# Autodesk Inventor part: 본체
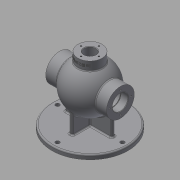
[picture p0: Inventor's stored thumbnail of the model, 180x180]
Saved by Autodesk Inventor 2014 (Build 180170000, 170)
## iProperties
Created: 2020-08
Part Number: 본체
Material: Generic
Document SubType Name: Modeling
Designer: kh
Density: 1 g/cm^3
Appearance: Default
Author: kh
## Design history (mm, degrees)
sketch "Sketch1"
  geometry: C1 r 85 at (0, 0); 1 further point
  constraints: 1 centre point, 1 coincident
  dimensions: "d0" = 170 diameter of C1
extrude "Extrusion1" new body sketch "Sketch1" distance "d1" = 10; taper "d2" = 0 deg
sketch "Sketch2"
  geometry: A1 r 72.5 centre (0, 0) between (0, 72.5) and (-72.5, 0); 3 further points
  constraints: 4 point on circle, 2 horizontal alignment, 2 vertical alignment, 1 centre point, 1 coincident
  dimensions: "d3" = 145 diameter of A1
hole "Hole1" sketch "Sketch2" at (0, 72.5), (-72.5, 0), (0, -72.5), (72.5, 0) diameter "d4" = 9; stored, may be unused: countersink angle "d8" = 90 deg, drill point angle "d10" = 118 deg; dims "d5" = 6, "d6" = 4, "d7" = 2, "d9" = 8
sketch "Sketch3"
  geometry: L1 (68, 10)-(68, 0) reference; L2 (68, 0)-(-68, 0) reference; L3 (-68, 0)-(-68, 10) reference; L4 (-68, 10)-(68, 10) reference; L5 (-85, 0)-(-85, 10) reference; L6 (-85, 10)-(-77, 10) reference; L7 (-77, 10)-(-77, 0) reference; L8 (-77, 0)-(-85, 0) reference; L9 (85, 10)-(85, 0) reference; L10 (85, 0)-(77, 0) reference; L11 (77, 0)-(77, 10) reference; L12 (77, 10)-(85, 10) reference; L13 (-53, 85)-(53, 85); A1 r 53 centre (0, 85) between (-53, 85) and (53, 85); 3 further points
  constraints: 2 end point, 2 midpoint, 2 point on circle, 1 centre point, 1 coincident, 1 parallel, 1 vertical alignment
  dimensions: "d11" = 85 distance of point (0, 0) A1.centre; "d12" = 106 diameter of A1
revolve "Revolution1" sketch "Sketch3" stored, may be unused: angle "d13" = 90 deg
workplane "Work Plane1"
sketch "Sketch4"
  geometry: L1 (51, 10)-(51, 0) reference; L2 (51, 0)-(0, 0) reference; L3 (0, 10)-(0, 0) reference; L4 (-51, 10)-(0, 10) reference; L5 (-51, 0)-(-51, 10) reference; L6 (0, 0)-(-51, 0) reference; L7 (0, 10)-(51, 10) reference; L8 (-85, 0)-(85, 0) reference; C1 r 31 at (0, 85)
  constraints: 1 centre point, 1 vertical alignment
  dimensions: "d15" = 62 diameter of C1; "d16" = 85 distance from line of L8 C1.centre
extrude "Extrusion2" join sketch "Sketch4" stored distance "d17" = 10; taper "d18" = 0 deg
mirror "Mirror1"
sketch "Sketch5"
  geometry: C1 r 31 at (0, 0) reference; C2 r 17.5 at (0, 0); 1 further point
  constraints: 1 centre point, 1 coincident
  dimensions: "d19" = 35 diameter of C2
extrude "Extrusion3" cut sketch "Sketch5" stored distance "d20" = 10; taper "d21" = 0 deg
sketch "Sketch6"
  geometry: L1 (-68, 0)-(-68, 10) reference; L2 (-68, 10)-(68, 10) reference; L3 (68, 10)-(68, 0) reference; L4 (68, 0)-(-68, 0) reference; L5 (85, 10)-(85, 0) reference; L6 (85, 0)-(77, 0) reference; L7 (77, 0)-(77, 10) reference; L8 (77, 10)-(85, 10) reference; L9 (-85, 0)-(-85, 10) reference; L10 (-85, 10)-(-77, 10) reference; L11 (-77, 10)-(-77, 0) reference; L12 (-77, 0)-(-85, 0) reference; L13 (-68, 116)-(-42.988, 116) reference; L14 (42.988, 116)-(68, 116) reference; L15 (68, 116)-(68, 102.5) reference; L16 (68, 102.5)-(-68, 102.5) reference; L17 (-68, 102.5)-(-68, 116) reference; L18 (-42.988, 54)-(-68, 54) reference; L19 (-68, 54)-(-68, 67.5) reference; L20 (-68, 67.5)-(68, 67.5) reference; L21 (68, 67.5)-(68, 54) reference; L22 (68, 54)-(42.988, 54) reference; L23 (-68, 85)-(68, 85); L24 (-52, 102.5)-(-50.25, 102.5); L25 (-50.25, 102.5)-(-50.25, 103.5); L26 (-50.25, 103.5)-(-52, 103.5); L27 (-52, 103.5)-(-52, 102.5); A1 r 53 centre (0, 85) between (42.988, 116) and (-42.988, 116) reference; A2 r 53 centre (0, 85) between (-42.988, 54) and (42.988, 54) reference; 2 further points
  constraints: 10 end point, 3 parallel, 1 coincident, 1 horizontal, 1 midpoint, 1 perpendicular, 1 point on line
  dimensions: "d22" = 16 distance between parallel lines of L27 L17; "d23" = 1.75 distance of L25.end L26.end; "d24" = 37 diameter of L26 L23
revolve "Revolution2" sketch "Sketch6" stored, may be unused: angle "d25" = 90 deg
workplane "Work Plane2"
sketch "Sketch7"
  geometry: C1 r 27 at (0, 0); 1 further point
  constraints: 1 centre point, 1 coincident
  dimensions: "d27" = 54 diameter of C1
extrude "Extrusion4" join sketch "Sketch7" stored distance "d28" = 10; taper "d29" = 0 deg
sketch "Sketch9"
  geometry: L1 (68, 102.5)-(-50.25, 102.5) reference; L2 (-50.25, 102.5)-(-50.25, 103.5) reference; L3 (-50.25, 103.5)-(-52, 103.5) reference; L4 (-52, 103.5)-(-52, 102.5) reference; L5 (-52, 102.5)-(-68, 102.5) reference; L6 (-68, 102.5)-(-68, 116) reference; L7 (-68, 116)-(-42.988, 116) reference; L8 (-27, 130.607)-(-27, 150) reference; L9 (-27, 150)-(27, 150) reference; L10 (27, 150)-(27, 130.607) reference; L11 (42.988, 116)-(68, 116) reference; L12 (68, 116)-(68, 102.5) reference; L13 (-42.988, 54)-(-68, 54) reference; L14 (-68, 54)-(-68, 67.5) reference; L15 (-68, 67.5)-(-52, 67.5) reference; L16 (-52, 67.5)-(-52, 66.5) reference; L17 (-52, 66.5)-(-50.25, 66.5) reference; L18 (-50.25, 66.5)-(-50.25, 67.5) reference; L19 (-50.25, 67.5)-(68, 67.5) reference; L20 (68, 67.5)-(68, 54) reference; L21 (68, 54)-(42.988, 54) reference; L22 (-77, 10)-(-77, 0) reference; L23 (-77, 0)-(-85, 0) reference; L24 (-85, 0)-(-85, 10) reference; L25 (-85, 10)-(-77, 10) reference; L26 (68, 10)-(68, 0) reference; L27 (68, 0)-(-68, 0) reference; L28 (-68, 0)-(-68, 10) reference; L29 (-68, 10)-(68, 10) reference; L30 (77, 0)-(77, 10) reference; L31 (77, 10)-(85, 10) reference; L32 (85, 10)-(85, 0) reference; L33 (85, 0)-(77, 0) reference; L34 (-43, 85)-(43, 85); A1 r 53 centre (0, 85) between (-27, 130.607) and (-42.988, 116) reference; A2 r 53 centre (0, 85) between (42.988, 116) and (27, 130.607) reference; A3 r 53 centre (0, 85) between (-42.988, 54) and (42.988, 54) reference; A4 r 43 centre (0, 85) between (-43, 85) and (43, 85); 1 further point
  constraints: 2 end point, 2 point on circle, 1 centre point, 1 coincident, 1 midpoint, 1 parallel
  dimensions: "d31" = 86 diameter of A4
revolve "Revolution3" sketch "Sketch9" stored, may be unused: angle "d32" = 90 deg
sketch "Sketch8"
  geometry: C1 r 13 at (0, 0); 1 further point
  constraints: 1 centre point, 1 coincident
  dimensions: "d30" = 26 diameter of C1
extrude "Extrusion5" cut sketch "Sketch8" stored distance "d33" = 10; taper "d34" = 0 deg
workplane "Work Plane3"
sketch "Sketch10"
  geometry: L1 (-20.739, 144.002)-(20.739, 144.002); L2 (20.739, 144.002)-(20.739, 137.998); L3 (20.739, 137.998)-(-20.739, 137.998); L4 (-20.739, 137.998)-(-20.739, 144.002); L5 (-20.739, 144.002)-(20.739, 137.998); L6 (-27, 130.607)-(27, 130.607) reference; L7 (-27, 150)-(27, 150) reference; 2 further points
  constraints: 2 end point, 1 midpoint, 2 other
  dimensions: "d36" = 27 horizontal distance of point (0, 141) L7.start; "d37" = 9 distance from line of point (0, 141) L7
emboss "Emboss1" sketch "Sketch10" dims "d2" = 0, "d38" = 0.5, "d39" = 0
sketch "Sketch11" dims "d40" = 48
  geometry: C1 r 17.5 at (0, 0) reference; C2 r 31 at (0, 0) reference; 3 further points
  constraints: 2 vertical alignment, 1 coincident, 2 other
hole "Hole2" sketch "Sketch11" at (0, 24) diameter "d41" = 3.242; stored, may be unused: countersink angle "d45" = 90 deg, drill point angle "d47" = 118 deg; dims "d42" = 12, "d43" = 4, "d44" = 2, "d46" = 15
pattern_circular "Circular Pattern1" dims angle "d49" = 360 deg
mirror "Mirror2"
sketch "Sketch12"
  geometry: L1 (-52, -4)-(52, -4); L2 (52, -4)-(52, 4); L3 (52, 4)-(-52, 4); L4 (-52, 4)-(-52, -4); L5 (-52, -4)-(52, 4); L6 (52, -4)-(-52, 4); L7 (4, 43)-(-4, 43); L8 (-4, 43)-(-4, -43); L9 (-4, -43)-(4, -43); L10 (4, -43)-(4, 43); L11 (4, 43)-(-4, -43); L12 (-4, 43)-(4, -43); 1 further point
  constraints: 24 end point, 4 midpoint, 4 parallel, 2 horizontal, 2 perpendicular
  dimensions: "d51" = 104 distance of L3.end L2.end; "d52" = 8 distance of L1.end L2.end; "d53" = 8 distance of L9.end L8.end; "d54" = 86 distance of L7.end L8.end
extrude "Extrusion6" join sketch "Sketch12" stored distance "d55" = 10; taper "d56" = 0 deg
sketch "Sketch13" dims "d57" = 40
  geometry: C1 r 13 at (0, 0) reference; C2 r 27 at (0, 0) reference; 3 further points
  constraints: 2 vertical alignment, 1 coincident, 2 other
hole "Hole3" sketch "Sketch13" at (0, 20) diameter "d58" = 3.242; stored, may be unused: countersink angle "d62" = 90 deg, drill point angle "d64" = 118 deg; dims "d59" = 12, "d60" = 4, "d61" = 2, "d63" = 15
pattern_circular "Circular Pattern2" dims angle "d66" = 360 deg
chamfer "Chamfer1" distance "d68" = 1; stored, may be unused: second distance "d69" = 2, angle "d70" = 45 deg
fillet "Fillet1" dims "d71" = 3
fillet "Fillet2" dims "d72" = 3
fillet "Fillet3" dims "d73" = 3
fillet "Fillet4" dims "d74" = 3
body "Solid1"
node "Projected Loop1"
node "Projected Loop2"
node "Projected Loop3"
node "Projected Loop4"
node "Project Cut Edges1"
node "Project Cut Edges2"
node "Project Cut Edges3"
node "Project Cut Edges4"
other parameters: "d14" = 68, "d35" = -44
